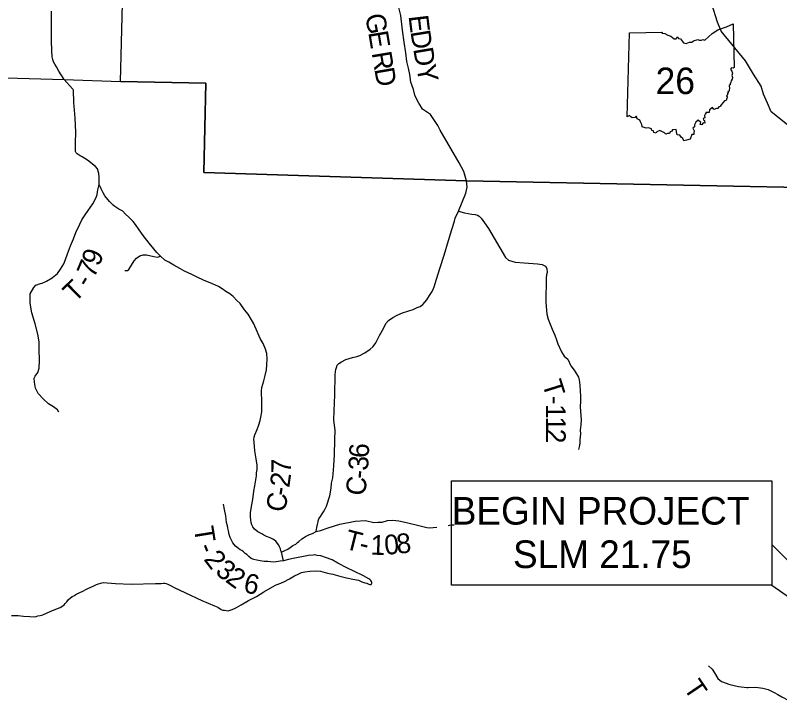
# Model space of a CAD drawing. Extents: x -15 to 405, y -40 to 87.
# Drawn here: x -11.716 to -9.391, y 36.316 to 38.387 of the extents above; entities that cross this region are included whole.
import ezdxf

# ---------------------------------------------------------------- set-up
doc = ezdxf.new("R2010")
doc.units = 0
for name, color, linetype in [('GM_P_State_Location', 7, 'Continuous'), ('GM_X_Major_Lake_Text', 7, 'Continuous'), ('GM_X_Minor_Lake', 7, 'Continuous'), ('GM_X_Minor_River', 7, 'Continuous'), ('GM_X_Rail_Line', 7, 'Continuous'), ('GM_X_State_Location', 7, 'Continuous'), ('GM_X_State_Shield', 7, 'Continuous'), ('GM_X_Township_Text', 7, 'Continuous')]:
    doc.layers.add(name, color=color, linetype=linetype)

msp = doc.modelspace()

# ---------------------------------------------------------------- linework, layer by layer
at = {"layer": 'GM_P_State_Location'}
for points in [[(-11.6026, 37.59), (-11.5881, 37.6022), (-11.5787, 37.6156), (-11.5688, 37.6317), (-11.5629, 37.6446), (-11.5571, 37.6619), (-11.5481, 37.6865), (-11.5391, 37.7071), (-11.5317, 37.7268), (-11.52, 37.7526), (-11.5133, 37.7655), (-11.503, 37.7809), (-11.4944, 37.7938), (-11.4801, 37.8144), (-11.4699, 37.833), (-11.4668, 37.8422), (-11.4654, 37.8563), (-11.4614, 37.8729)], [(-10.3682, 37.7921), (-10.3504, 37.7862), (-10.3277, 37.7828), (-10.3175, 37.7814), (-10.3108, 37.7798), (-10.3054, 37.7767), (-10.2989, 37.7705), (-10.2894, 37.7567), (-10.2771, 37.7389), (-10.2249, 37.6512), (-10.2159, 37.6426), (-10.1958, 37.6371), (-10.1683, 37.6346), (-10.1276, 37.6316), (-10.1136, 37.6296), (-10.1041, 37.6246), (-10.0996, 37.6171), (-10.099, 37.6054), (-10.101, 37.5982), (-10.1021, 37.589), (-10.1024, 37.514), (-10.0999, 37.479), (-10.0954, 37.4634), (-10.0893, 37.4482), (-10.0832, 37.4326), (-10.0754, 37.415), (-10.0701, 37.401), (-10.0664, 37.3886), (-10.0555, 37.3646), (-10.0469, 37.351), (-10.0357, 37.3415), (-10.0263, 37.3219), (-10.0162, 37.3084), (-10.011, 37.3), (-10.0061, 37.292), (-10.0037, 37.2872), (-10.0012, 37.2792), (-9.9995, 37.2624), (-9.9986, 37.2447), (-9.9977, 37.2303), (-9.9972, 37.2143), (-9.9982, 37.1967), (-9.9952, 37.1574), (-9.9959, 37.1426), (-9.9978, 37.1265), (-9.9977, 37.1145), (-9.9996, 37.0968), (-9.9991, 37.0888), (-9.9999, 37.0796), (-10.0034, 37.0672)], [(-10.9004, 36.7293), (-10.9107, 36.7277), (-10.9223, 36.7257), (-10.9307, 36.7252), (-10.9395, 36.7259), (-10.9483, 36.7271), (-10.9591, 36.727), (-10.9712, 36.7289), (-10.9812, 36.7305), (-10.9904, 36.7324), (-10.9989, 36.736), (-11.0057, 36.7415), (-11.0118, 36.7479), (-11.017, 36.7511), (-11.0218, 36.7563), (-11.0271, 36.7598), (-11.0319, 36.7626), (-11.0375, 36.7666), (-11.046, 36.7737), (-11.0545, 36.7833), (-11.0589, 36.7917), (-11.0622, 36.8001), (-11.0655, 36.8089), (-11.0675, 36.8201), (-11.0696, 36.8277), (-11.0708, 36.8353), (-11.0733, 36.8449), (-11.0759, 36.8657), (-11.08, 36.8845), (-11.0825, 36.9009)], [(-10.8006, 36.818), (-10.7883, 36.8215), (-10.7647, 36.8293), (-10.7291, 36.8403), (-10.6823, 36.8495), (-10.6515, 36.8517), (-10.6262, 36.8458), (-10.6134, 36.8459), (-10.6001, 36.8464), (-10.5845, 36.8513), (-10.5681, 36.8522), (-10.5501, 36.8503), (-10.526, 36.8453), (-10.4847, 36.8351), (-10.4642, 36.8301), (-10.4554, 36.8289), (-10.445, 36.8298), (-10.4343, 36.8314)], [(-10.3994, 36.8366), (-10.3913, 36.8378), (-10.3816, 36.8387)], [(-9.6084, 36.4098), (-9.5971, 36.3995), (-9.5902, 36.3879), (-9.5797, 36.3707), (-9.5688, 36.3616), (-9.5427, 36.3525), (-9.5166, 36.3467), (-9.4914, 36.3441), (-9.487, 36.3441), (-9.4637, 36.3446), (-9.4429, 36.3416), (-9.4268, 36.3373), (-9.4087, 36.329), (-9.3971, 36.3222), (-9.3846, 36.3159), (-9.3661, 36.3052), (-9.3403, 36.3064)]]:
    msp.add_lwpolyline(points, dxfattribs=at)
at = {"layer": 'GM_X_Major_Lake_Text'}
for points in [[(-11.3827, 37.6113), (-11.3751, 37.6115), (-11.3704, 37.6145), (-11.3543, 37.6404), (-11.3472, 37.6484), (-11.3377, 37.6562), (-11.3275, 37.6592), (-11.3168, 37.6592), (-11.2951, 37.6538), (-11.2832, 37.6523), (-11.2747, 37.6551)], [(-11.5836, 37.1812), (-11.5877, 37.1879), (-11.5999, 37.197), (-11.6152, 37.2065), (-11.6298, 37.22), (-11.6468, 37.2378), (-11.655, 37.2534), (-11.6576, 37.2722), (-11.6585, 37.2837), (-11.6556, 37.2901), (-11.6471, 37.3008), (-11.6432, 37.3149), (-11.6422, 37.3373), (-11.6438, 37.371), (-11.6437, 37.3943), (-11.6479, 37.4175), (-11.6555, 37.4491), (-11.6658, 37.4827), (-11.671, 37.5123), (-11.6705, 37.54), (-11.6598, 37.5594), (-11.6539, 37.567), (-11.6395, 37.5714), (-11.6347, 37.5729), (-11.6208, 37.579), (-11.604, 37.5888), (-11.6026, 37.59)]]:
    msp.add_lwpolyline(points, dxfattribs=at)
at = {"layer": 'GM_X_Rail_Line'}
for points in [[(-5.8735, 37.6193), (-6.746, 37.6435), (-7.1795, 37.6523), (-7.1958, 37.2443), (-7.727, 37.2683), (-7.6952, 37.7971), (-8.9152, 37.8499), (-9.0187, 37.8511), (-9.126, 37.86), (-10.3436, 37.8843), (-11.1424, 37.9093), (-11.1367, 38.1803), (-11.3964, 38.1863), (-11.3573, 39.6853), (-11.313, 41.3844), (-11.2938, 42.1225)], [(-13.0124, 38.5078), (-13.0163, 38.2592), (-13.0272, 37.9582), (-12.9808, 37.9596), (-12.7335, 37.9524), (-12.0896, 37.9336), (-11.9282, 37.9289), (-11.9246, 38.2025), (-11.5671, 38.1915), (-11.3964, 38.1863), (-11.1367, 38.1803), (-11.1424, 37.9093), (-10.3436, 37.8843), (-9.126, 37.86)]]:
    msp.add_lwpolyline(points, dxfattribs=at)
at = {"layer": 'GM_X_State_Location'}
for p, q in [((-9.8551, 38.0789), (-9.8479, 38.3342)), ((-10.3893, 36.6548), (-10.3893, 36.9723)), ((-10.3893, 36.9723), (-9.4155, 36.9723)), ((-9.4155, 36.9723), (-9.4155, 36.6548)), ((-9.4155, 36.6548), (-10.3893, 36.6548))]:
    msp.add_line(p, q, dxfattribs=at)
for points in [[(-9.3682, 38.054), (-9.4174, 38.0933), (-9.4291, 38.1195), (-9.4412, 38.1478), (-9.448, 38.1718), (-9.4707, 38.2079), (-9.4954, 38.2488), (-9.5695, 38.3386), (-9.5804, 38.3661), (-9.5982, 38.4204)], [(-9.8479, 38.3342), (-9.7489, 38.3358), (-9.7504, 38.3327), (-9.7411, 38.3321), (-9.7312, 38.3266), (-9.7228, 38.3232), (-9.7125, 38.3151), (-9.7064, 38.3151), (-9.7038, 38.3218), (-9.6991, 38.3167), (-9.6935, 38.3157), (-9.6838, 38.3035), (-9.6758, 38.3009), (-9.6663, 38.3051), (-9.6592, 38.3058), (-9.6539, 38.3099), (-9.6404, 38.3134), (-9.6365, 38.3113), (-9.6294, 38.3118), (-9.6257, 38.3133), (-9.6195, 38.3119), (-9.6084, 38.3212), (-9.5971, 38.3322), (-9.5796, 38.3425), (-9.5535, 38.3522), (-9.5328, 38.361), (-9.5298, 38.2285)], [(-9.5298, 38.2285), (-9.5328, 38.2267), (-9.5376, 38.2276), (-9.5407, 38.2238), (-9.5368, 38.2176), (-9.535, 38.2111), (-9.5366, 38.2039), (-9.535, 38.1979), (-9.5361, 38.1929), (-9.539, 38.188), (-9.5401, 38.1833), (-9.5426, 38.1783), (-9.5425, 38.1755), (-9.5448, 38.1733), (-9.5444, 38.165), (-9.5456, 38.1604), (-9.5452, 38.1564), (-9.5491, 38.1554), (-9.5482, 38.1521), (-9.5507, 38.1496), (-9.5502, 38.1453), (-9.553, 38.1425), (-9.5503, 38.1369), (-9.5525, 38.1352), (-9.5543, 38.1284), (-9.5594, 38.127), (-9.5694, 38.1147), (-9.573, 38.11), (-9.5769, 38.1088), (-9.5792, 38.104), (-9.5841, 38.104), (-9.5915, 38.1007), (-9.5963, 38.1064), (-9.6047, 38.0995), (-9.6057, 38.0915), (-9.6164, 38.0918), (-9.616, 38.0878), (-9.6184, 38.0866), (-9.6205, 38.0826), (-9.6193, 38.0754), (-9.6243, 38.0736), (-9.6237, 38.0694), (-9.6204, 38.0669), (-9.619, 38.0589), (-9.6243, 38.0605), (-9.6286, 38.0538), (-9.6331, 38.0554), (-9.6317, 38.0611), (-9.6392, 38.0679), (-9.6463, 38.0625), (-9.6501, 38.0537), (-9.6501, 38.0478), (-9.6555, 38.0443), (-9.652, 38.036), (-9.6527, 38.0303), (-9.6525, 38.0248), (-9.6592, 38.0251), (-9.6633, 38.0103)], [(-9.6633, 38.0103), (-9.6748, 38.0075), (-9.6828, 38.0059), (-9.6856, 38.0125), (-9.6914, 38.0161), (-9.6951, 38.0228), (-9.7033, 38.0237), (-9.7053, 38.0329), (-9.7062, 38.0403), (-9.7175, 38.0385), (-9.7205, 38.0339), (-9.7246, 38.0327), (-9.7269, 38.0281), (-9.7323, 38.0277), (-9.7382, 38.0256), (-9.742, 38.0301), (-9.7516, 38.0346), (-9.7559, 38.0369), (-9.7649, 38.0333), (-9.7668, 38.029), (-9.774, 38.0309), (-9.7757, 38.0357), (-9.78, 38.0372), (-9.7809, 38.0422), (-9.7902, 38.045), (-9.7973, 38.0439), (-9.8098, 38.0479), (-9.8106, 38.0546), (-9.8148, 38.0628), (-9.817, 38.0684), (-9.8249, 38.0728), (-9.8266, 38.0795), (-9.8291, 38.0793), (-9.8314, 38.0766), (-9.8402, 38.0753), (-9.8437, 38.078), (-9.8486, 38.0828), (-9.8551, 38.0789)]]:
    msp.add_lwpolyline(points, dxfattribs=at)
msp.add_lwpolyline([(-9.0006, 36.366), (-9.4155, 36.7781), (-9.4155, 36.6548)], close=True, dxfattribs=at)
at = {"layer": 'GM_X_Township_Text'}
for points in [[(-10.4236, 38.0382), (-10.4313, 38.0517), (-10.4536, 38.0854), (-10.4781, 38.1016), (-10.4847, 38.1136), (-10.4884, 38.12), (-10.4949, 38.1311), (-10.5011, 38.1443), (-10.5054, 38.1619), (-10.5129, 38.1842), (-10.516, 38.2071), (-10.5202, 38.2263), (-10.5249, 38.2471), (-10.5289, 38.2727), (-10.5337, 38.3055), (-10.5386, 38.342), (-10.5436, 38.3868), (-10.5508, 38.4152)], [(-11.5674, 38.1921), (-11.5833, 38.2171), (-11.5907, 38.2303), (-11.5961, 38.2386), (-11.5993, 38.2454), (-11.6022, 38.2526), (-11.6036, 38.261), (-11.605, 38.2798), (-11.6054, 38.3099), (-11.6062, 38.3994)], [(-10.9063, 36.7549), (-10.9084, 36.7592), (-10.9096, 36.7648), (-10.9129, 36.7712), (-10.9146, 36.7764), (-10.9219, 36.7859), (-10.924, 36.7887), (-10.9276, 36.7915), (-10.9325, 36.7946), (-10.9405, 36.7985), (-10.9522, 36.8028), (-10.9599, 36.8071), (-10.9663, 36.8106), (-10.972, 36.8137), (-10.978, 36.8165), (-10.9849, 36.8216), (-10.9889, 36.8255), (-10.9934, 36.8319), (-10.9963, 36.8379), (-10.9988, 36.8451), (-11.0001, 36.8535), (-11.0006, 36.8627), (-11.0004, 36.8743), (-10.9979, 36.8944), (-10.9941, 36.9153), (-10.9901, 36.941), (-10.9875, 36.9567), (-10.9845, 36.9752), (-10.9823, 36.9872), (-10.982, 36.9968), (-10.9809, 37.0069), (-10.9807, 37.0193), (-10.9837, 37.0389), (-10.9873, 37.0633), (-10.9896, 37.0898), (-10.9901, 37.099), (-10.9894, 37.105), (-10.9871, 37.1122), (-10.9801, 37.1284), (-10.9751, 37.1425), (-10.9712, 37.1554), (-10.969, 37.1654), (-10.9664, 37.1815), (-10.9658, 37.1987), (-10.9665, 37.2204), (-10.9671, 37.2368), (-10.9672, 37.246), (-10.9661, 37.2553), (-10.9604, 37.2762), (-10.9566, 37.2923), (-10.9524, 37.3092), (-10.9506, 37.3241), (-10.9501, 37.3433), (-10.9515, 37.3589), (-10.9553, 37.3725), (-10.9623, 37.3893), (-10.9709, 37.4044), (-10.9808, 37.4263), (-10.9911, 37.449), (-11.0014, 37.4682), (-11.0079, 37.4789), (-11.0189, 37.4916), (-11.032, 37.5111), (-11.0421, 37.5202), (-11.0531, 37.532), (-11.0632, 37.5399), (-11.0753, 37.547), (-11.0867, 37.5553), (-11.0984, 37.5623), (-11.1161, 37.5705), (-11.1435, 37.5818), (-11.1628, 37.5908), (-11.1794, 37.599), (-11.2011, 37.6091), (-11.2153, 37.617), (-11.2342, 37.6271), (-11.2488, 37.6362), (-11.2613, 37.6428), (-11.2747, 37.6551), (-11.2856, 37.6662), (-11.2946, 37.6769), (-11.3092, 37.6947), (-11.3272, 37.7182), (-11.339, 37.7349), (-11.35, 37.7508), (-11.3578, 37.7599), (-11.3635, 37.7662), (-11.3708, 37.7738), (-11.3805, 37.7825), (-11.3894, 37.7916), (-11.4015, 37.7978), (-11.4129, 37.8057), (-11.4185, 37.8104), (-11.4295, 37.8211), (-11.4433, 37.8382), (-11.4483, 37.847), (-11.4548, 37.8597), (-11.4614, 37.8729), (-11.4608, 37.8857), (-11.4613, 37.8953), (-11.4615, 37.9066), (-11.466, 37.9205), (-11.4721, 37.9273), (-11.496, 37.9466), (-11.513, 37.9568), (-11.5186, 37.96), (-11.5219, 37.9623), (-11.5243, 37.9635), (-11.5275, 37.9655), (-11.5288, 37.9667), (-11.5312, 37.9694), (-11.5332, 37.9726), (-11.5333, 37.981), (-11.5328, 37.9995), (-11.532, 38.032), (-11.5338, 38.0741), (-11.5371, 38.111), (-11.5376, 38.121), (-11.5377, 38.1274), (-11.5392, 38.1539), (-11.5385, 38.1567), (-11.5385, 38.1599), (-11.5398, 38.1619), (-11.5422, 38.1639), (-11.5671, 38.1915), (-11.5674, 38.1921)], [(-10.4443, 37.5566), (-10.4422, 37.5618), (-10.4349, 37.5851), (-10.4237, 37.6202), (-10.4122, 37.658), (-10.3984, 37.7027), (-10.3884, 37.7362), (-10.3803, 37.7615), (-10.3784, 37.77), (-10.3682, 37.7921), (-10.3455, 37.8464), (-10.3416, 37.8643), (-10.3436, 37.8843), (-10.3525, 37.9119), (-10.3663, 37.9386), (-10.4236, 38.0382)], [(-10.6627, 37.3556), (-10.6531, 37.3613), (-10.6372, 37.3723), (-10.6273, 37.3808), (-10.6194, 37.3914), (-10.6081, 37.4136), (-10.5956, 37.437), (-10.5893, 37.4499), (-10.581, 37.4597), (-10.5683, 37.4687), (-10.5548, 37.476), (-10.5389, 37.4823), (-10.5197, 37.4889), (-10.5058, 37.4931), (-10.4938, 37.4985), (-10.4851, 37.5022), (-10.4771, 37.5084), (-10.4645, 37.5226), (-10.4562, 37.5351), (-10.4483, 37.5475), (-10.4472, 37.5493), (-10.4443, 37.5566)], [(-10.9063, 36.7549), (-10.8963, 36.7598), (-10.8872, 36.7643), (-10.88, 36.7696), (-10.8721, 36.775), (-10.863, 36.7799), (-10.8574, 36.7844), (-10.8534, 36.788), (-10.8447, 36.7954), (-10.8396, 36.7986), (-10.8332, 36.8023), (-10.8213, 36.8085), (-10.8125, 36.8122), (-10.8006, 36.818), (-10.7991, 36.8304), (-10.7972, 36.8393), (-10.7953, 36.8469), (-10.7946, 36.8501), (-10.7927, 36.8566), (-10.7883, 36.8635), (-10.7828, 36.8716), (-10.7785, 36.8776), (-10.7742, 36.8853), (-10.7699, 36.895), (-10.7591, 36.926), (-10.7554, 36.9493), (-10.7548, 36.9653), (-10.7502, 36.981), (-10.7471, 37.0172), (-10.7451, 37.0513), (-10.7441, 37.097), (-10.7437, 37.1259), (-10.7469, 37.1567), (-10.7465, 37.1852), (-10.7447, 37.2329), (-10.7431, 37.2943), (-10.742, 37.3043), (-10.7409, 37.3104), (-10.739, 37.3164), (-10.7367, 37.3233), (-10.7324, 37.3289), (-10.724, 37.3339), (-10.7113, 37.3404), (-10.6905, 37.3467), (-10.6769, 37.3497), (-10.6687, 37.3529), (-10.665, 37.3543), (-10.6627, 37.3556)], [(-10.6471, 36.6605), (-10.6455, 36.6601), (-10.6445, 36.6596), (-10.6414, 36.6581), (-10.6378, 36.657), (-10.6342, 36.6566), (-10.6314, 36.6607), (-10.6319, 36.6635), (-10.6331, 36.6662), (-10.6344, 36.6686), (-10.638, 36.6722), (-10.6408, 36.6746), (-10.6574, 36.6832), (-10.6864, 36.6976), (-10.7078, 36.7078), (-10.7356, 36.7218), (-10.7522, 36.732), (-10.7723, 36.7394), (-10.7864, 36.744), (-10.798, 36.7455), (-10.8052, 36.7466), (-10.8104, 36.7465), (-10.824, 36.7447), (-10.8712, 36.7361), (-10.8848, 36.7331), (-10.9004, 36.7293), (-10.9063, 36.7549)], [(-11.2243, 36.644), (-11.2237, 36.6437), (-11.2155, 36.6398), (-11.1834, 36.6245), (-11.1492, 36.6086), (-11.1105, 36.5918), (-11.0996, 36.5876), (-11.0895, 36.5809), (-11.0847, 36.5793), (-11.0795, 36.5786), (-11.0746, 36.5775), (-11.069, 36.5767), (-11.0626, 36.5784), (-11.0562, 36.5805), (-11.0491, 36.5838), (-11.0435, 36.5867), (-11.0292, 36.5949), (-11.0069, 36.6084), (-10.9827, 36.6208), (-10.96, 36.6347), (-10.9338, 36.6499), (-10.9222, 36.6556), (-10.9089, 36.6607), (-10.9061, 36.6617), (-10.8991, 36.6648), (-10.8824, 36.6738), (-10.8673, 36.6828), (-10.8553, 36.6882), (-10.8458, 36.6931), (-10.8354, 36.6953), (-10.8206, 36.6979), (-10.8014, 36.6981), (-10.7878, 36.6971), (-10.7669, 36.6913), (-10.75, 36.688), (-10.7291, 36.6818), (-10.709, 36.6769), (-10.6897, 36.6731), (-10.672, 36.6701), (-10.6619, 36.6651), (-10.6531, 36.662), (-10.6471, 36.6605)], [(-11.7278, 36.5629), (-11.707, 36.5624), (-11.691, 36.561), (-11.6713, 36.5596), (-11.6565, 36.5586), (-11.6521, 36.5599), (-11.6473, 36.5616), (-11.6401, 36.5625), (-11.6325, 36.5646), (-11.6102, 36.5745), (-11.5875, 36.5836), (-11.5799, 36.5865), (-11.574, 36.5898), (-11.5672, 36.5955), (-11.5641, 36.5987), (-11.5593, 36.604), (-11.5538, 36.6113), (-11.5494, 36.615), (-11.5431, 36.6202), (-11.5375, 36.6227), (-11.5288, 36.6285), (-11.5125, 36.6359), (-11.4977, 36.6437), (-11.4866, 36.6486), (-11.4794, 36.6519), (-11.4754, 36.6536), (-11.4687, 36.6569), (-11.4631, 36.659), (-11.4486, 36.663), (-11.4114, 36.6597), (-11.3633, 36.6583), (-11.2892, 36.6596), (-11.278, 36.6598), (-11.272, 36.6599), (-11.2656, 36.6608), (-11.2612, 36.6608), (-11.2572, 36.6597), (-11.2499, 36.6566), (-11.2243, 36.644)]]:
    msp.add_lwpolyline(points, dxfattribs=at)

# ---------------------------------------------------------------- texts
at = {"layer": 'GM_X_Minor_Lake'}
for s, rotation, p in [('G', 280.6991, (-10.6526, 38.3868)), ('E', 276.7482, (-10.5203, 38.3848)), ('E', 279.506, (-10.6429, 38.3352)), ('D', 279.2017, (-10.5146, 38.3374)), ('D', 279.5248, (-10.5061, 38.285)), ('R', 279.4041, (-10.6325, 38.2727)), ('Y', 280.9364, (-10.4971, 38.2313)), ('D', 279.7772, (-10.6244, 38.2237)), ('6', 87.8006, (-10.6412, 37.0407)), ('7', 89.6524, (-10.8774, 36.9943)), ('3', 85.9289, (-10.6439, 37.0017)), ('2', 82.3367, (-10.8829, 36.9494)), ('C', 82.3981, (-10.653, 36.9243)), ('-', 85.0836, (-10.6461, 36.9762)), ('-', 80.7595, (-10.8872, 36.9233)), ('C', 80.4722, (-10.8954, 36.8743))]:
    msp.add_text(s, height=0.06, rotation=rotation, dxfattribs=at).set_placement(p)
at = {"layer": 'GM_X_Minor_River'}
for s, rotation, p in [('9', 68.8894, (-11.4612, 37.6213)), ('7', 67.5076, (-11.4759, 37.5857)), ('T', 44.5394, (-11.5351, 37.5114)), ('-', 59.208, (-11.4928, 37.556)), ('T', 287.4496, (-10.1146, 37.2684)), ('-', 269.4146, (-10.1019, 37.2305)), ('1', 269.7011, (-10.1021, 37.2055)), ('1', 270.561, (-10.1023, 37.1675)), ('2', 269.2454, (-10.102, 37.131)), ('T', 279.1199, (-11.1734, 36.8293)), ('T', 345.8203, (-10.7177, 36.7665)), ('1', 357.9839, (-10.6366, 36.7478)), ('0', 5.443, (-10.5911, 36.7467)), ('8', 5.3471, (-10.5543, 36.7502)), ('-', 292.0475, (-11.1623, 36.7708)), ('-', 346.4784, (-10.6735, 36.7553)), ('2', 306.9542, (-11.1447, 36.7332)), ('3', 321.551, (-11.1109, 36.6917)), ('2', 323.7695, (-11.0799, 36.6672)), ('6', 348.2573, (-11.0248, 36.6341)), ('T', 304.1227, (-9.6858, 36.3424))]:
    msp.add_text(s, height=0.06, rotation=rotation, dxfattribs=at).set_placement(p)
at = {"layer": 'GM_X_State_Location'}
for s, p in [('BEGIN PROJECT', (-10.3887, 36.8389)), ('SLM 21.75', (-10.2025, 36.7069))]:
    msp.add_text(s, height=0.084, dxfattribs=at).set_placement(p)
at = {"layer": 'GM_X_State_Shield'}
msp.add_text('26', height=0.08048, dxfattribs=at).set_placement((-9.7689, 38.1476))

doc.saveas('drawing.dxf')
